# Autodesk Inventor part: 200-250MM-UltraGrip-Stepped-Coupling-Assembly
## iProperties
Created: 2012-05
Part Number: 200-250MM-UltraGrip-Stepped-Coupling-Assembly
Document SubType Name: Modeling
Designer: D Cole
Density: 1 g/cm^3
Author: D Cole
